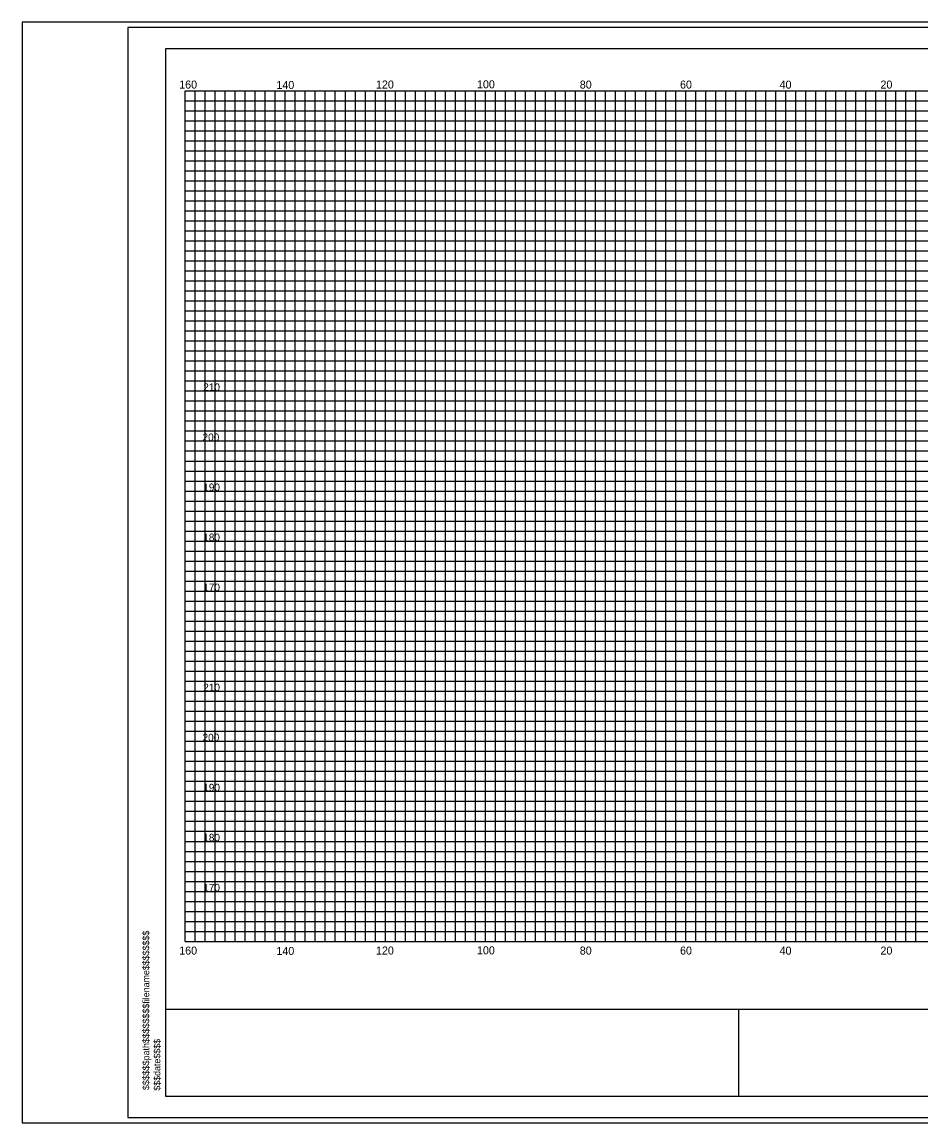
# Model space of a CAD drawing. Extents: x 967 to 1326, y 964 to 3144.
# Drawn here: x 967.4 to 1147, y 2083.7 to 2303.7 of the extents above; entities that cross this region are included whole.
import ezdxf

# ---------------------------------------------------------------- set-up
doc = ezdxf.new("R2010")
doc.units = 0
for name, color, linetype in [('Default', 7, 'Continuous'), ('RD_GPK_XS_Cell', 7, 'Continuous'), ('RD_XS_ExGround', 7, 'Continuous'), ('RD_XS_ExPaveRet', 7, 'Continuous'), ('RD_XS_Misc_Line', 7, 'Continuous'), ('RD_XS_TX_Elev_EX', 7, 'Continuous'), ('RD_XS_TX_Station', 7, 'Continuous')]:
    doc.layers.add(name, color=color, linetype=linetype)

msp = doc.modelspace()

# ---------------------------------------------------------------- linework, layer by layer
at = {"layer": 'RD_GPK_XS_Cell'}
for p, q in [((1000, 2290), (1320, 2290)), ((1000, 2120), (1000, 2290)), ((1010, 2120), (1010, 2290)), ((1020, 2120), (1020, 2290)), ((1030, 2120), (1030, 2290)), ((1040, 2120), (1040, 2290)), ((1050, 2120), (1050, 2290)), ((1060, 2120), (1060, 2290)), ((1070, 2120), (1070, 2290)), ((1080, 2120), (1080, 2290)), ((1090, 2120), (1090, 2290)), ((1100, 2120), (1100, 2290)), ((1110, 2120), (1110, 2290)), ((1120, 2120), (1120, 2290)), ((1130, 2120), (1130, 2290)), ((1140, 2120), (1140, 2290)), ((1000, 2280), (1320, 2280)), ((1000, 2270), (1320, 2270)), ((1000, 2260), (1320, 2260)), ((1000, 2250), (1320, 2250)), ((1000, 2240), (1320, 2240)), ((1000, 2230), (1320, 2230)), ((1000, 2220), (1320, 2220)), ((1000, 2210), (1320, 2210)), ((1000, 2200), (1320, 2200)), ((1000, 2190), (1320, 2190)), ((1000, 2180), (1320, 2180)), ((1000, 2170), (1320, 2170)), ((1000, 2160), (1320, 2160)), ((1000, 2150), (1320, 2150)), ((1000, 2140), (1320, 2140)), ((1000, 2130), (1320, 2130)), ((1000, 2120), (1320, 2120))]:
    msp.add_line(p, q, dxfattribs=at)
at = {"layer": 'RD_XS_ExGround'}
for p, q in [((1000, 2288), (1320, 2288)), ((1002, 2120), (1002, 2290)), ((1004, 2120), (1004, 2290)), ((1006, 2120), (1006, 2290)), ((1008, 2120), (1008, 2290)), ((1012, 2120), (1012, 2290)), ((1014, 2120), (1014, 2290)), ((1016, 2120), (1016, 2290)), ((1018, 2120), (1018, 2290)), ((1022, 2120), (1022, 2290)), ((1024, 2120), (1024, 2290)), ((1026, 2120), (1026, 2290)), ((1028, 2120), (1028, 2290)), ((1032, 2120), (1032, 2290)), ((1034, 2120), (1034, 2290)), ((1036, 2120), (1036, 2290)), ((1038, 2120), (1038, 2290)), ((1042, 2120), (1042, 2290)), ((1044, 2120), (1044, 2290)), ((1046, 2120), (1046, 2290)), ((1048, 2120), (1048, 2290)), ((1052, 2120), (1052, 2290)), ((1054, 2120), (1054, 2290)), ((1056, 2120), (1056, 2290)), ((1058, 2120), (1058, 2290)), ((1062, 2120), (1062, 2290)), ((1064, 2120), (1064, 2290)), ((1066, 2120), (1066, 2290)), ((1068, 2120), (1068, 2290)), ((1072, 2120), (1072, 2290)), ((1074, 2120), (1074, 2290)), ((1076, 2120), (1076, 2290)), ((1078, 2120), (1078, 2290)), ((1082, 2120), (1082, 2290)), ((1084, 2120), (1084, 2290)), ((1086, 2120), (1086, 2290)), ((1088, 2120), (1088, 2290)), ((1092, 2120), (1092, 2290)), ((1094, 2120), (1094, 2290)), ((1096, 2120), (1096, 2290)), ((1098, 2120), (1098, 2290)), ((1102, 2120), (1102, 2290)), ((1104, 2120), (1104, 2290)), ((1106, 2120), (1106, 2290)), ((1108, 2120), (1108, 2290)), ((1112, 2120), (1112, 2290)), ((1114, 2120), (1114, 2290)), ((1116, 2120), (1116, 2290)), ((1118, 2120), (1118, 2290)), ((1122, 2120), (1122, 2290)), ((1124, 2120), (1124, 2290)), ((1126, 2120), (1126, 2290)), ((1128, 2120), (1128, 2290)), ((1132, 2120), (1132, 2290)), ((1134, 2120), (1134, 2290)), ((1136, 2120), (1136, 2290)), ((1138, 2120), (1138, 2290)), ((1142, 2120), (1142, 2290)), ((1144, 2120), (1144, 2290)), ((1146, 2120), (1146, 2290)), ((1000, 2286), (1320, 2286)), ((1000, 2284), (1320, 2284)), ((1000, 2282), (1320, 2282)), ((1000, 2278), (1320, 2278)), ((1000, 2276), (1320, 2276)), ((1000, 2274), (1320, 2274)), ((1000, 2272), (1320, 2272)), ((1000, 2268), (1320, 2268)), ((1000, 2266), (1320, 2266)), ((1000, 2264), (1320, 2264)), ((1000, 2262), (1320, 2262)), ((1000, 2258), (1320, 2258)), ((1000, 2256), (1320, 2256)), ((1000, 2254), (1320, 2254)), ((1000, 2252), (1320, 2252)), ((1000, 2248), (1320, 2248)), ((1000, 2246), (1320, 2246)), ((1000, 2244), (1320, 2244)), ((1000, 2242), (1320, 2242)), ((1000, 2238), (1320, 2238)), ((1000, 2236), (1320, 2236)), ((1000, 2234), (1320, 2234)), ((1000, 2232), (1320, 2232)), ((1000, 2228), (1320, 2228)), ((1000, 2226), (1320, 2226)), ((1000, 2224), (1320, 2224)), ((1000, 2222), (1320, 2222)), ((1000, 2218), (1320, 2218)), ((1000, 2216), (1320, 2216)), ((1000, 2214), (1320, 2214)), ((1000, 2212), (1320, 2212)), ((1000, 2208), (1320, 2208)), ((1000, 2206), (1320, 2206)), ((1000, 2204), (1320, 2204)), ((1000, 2202), (1320, 2202)), ((1000, 2198), (1320, 2198)), ((1000, 2196), (1320, 2196)), ((1000, 2194), (1320, 2194)), ((1000, 2192), (1320, 2192)), ((1000, 2188), (1320, 2188)), ((1000, 2186), (1320, 2186)), ((1000, 2184), (1320, 2184)), ((1000, 2182), (1320, 2182)), ((1000, 2178), (1320, 2178)), ((1000, 2176), (1320, 2176)), ((1000, 2174), (1320, 2174)), ((1000, 2172), (1320, 2172)), ((1000, 2168), (1320, 2168)), ((1000, 2166), (1320, 2166)), ((1000, 2164), (1320, 2164)), ((1000, 2162), (1320, 2162)), ((1000, 2158), (1320, 2158)), ((1000, 2156), (1320, 2156)), ((1000, 2154), (1320, 2154)), ((1000, 2152), (1320, 2152)), ((1000, 2148), (1320, 2148)), ((1000, 2146), (1320, 2146)), ((1000, 2144), (1320, 2144)), ((1000, 2142), (1320, 2142)), ((1000, 2138), (1320, 2138)), ((1000, 2136), (1320, 2136)), ((1000, 2134), (1320, 2134)), ((1000, 2132), (1320, 2132)), ((1000, 2128), (1320, 2128)), ((1000, 2126), (1320, 2126)), ((1000, 2124), (1320, 2124)), ((1000, 2122), (1320, 2122))]:
    msp.add_line(p, q, dxfattribs=at)
at = {"layer": 'RD_XS_ExPaveRet'}
for points in [[(967.41, 2083.72), (1326.28, 2083.72), (1326.28, 2303.72), (967.41, 2303.72)], [(988.52, 2084.84), (1326.28, 2084.84), (1326.28, 2302.6), (988.52, 2302.6)]]:
    msp.add_lwpolyline(points, close=True, dxfattribs=at)
at = {"layer": 'RD_XS_TX_Elev_EX'}
for p, q in [((996.11, 2088.98), (996.11, 2298.46)), ((996.11, 2298.46), (1323.89, 2298.46)), ((996.11, 2106.49), (1323.89, 2106.49)), ((1110.59, 2088.98), (1110.59, 2106.56)), ((1323.89, 2088.98), (996.11, 2088.98))]:
    msp.add_line(p, q, dxfattribs=at)
at = {"layer": 'RD_XS_TX_Station'}
msp.add_lwpolyline([(967.41, 2083.72), (1326.28, 2083.72), (1326.28, 2303.72), (967.41, 2303.72)], close=True, dxfattribs=at)

# ---------------------------------------------------------------- texts
at = {"layer": 'Default'}
for s, p in [('210', (1003.61, 2230)), ('200', (1003.47, 2220)), ('190', (1003.61, 2210)), ('180', (1003.61, 2200)), ('170', (1003.61, 2190)), ('210', (1003.61, 2170)), ('200', (1003.47, 2160)), ('190', (1003.61, 2150)), ('180', (1003.61, 2140)), ('170', (1003.61, 2130))]:
    msp.add_text(s, height=1.5, dxfattribs=at).set_placement(p)
for s, p in [('$$$$$$path$$$$$$$$filename$$$$$$$$', (992.83, 2090.31)), ('$$$date$$$$', (995.04, 2090.17))]:
    msp.add_text(s, height=1.3258, rotation=90, dxfattribs=at).set_placement(p)
at = {"layer": 'RD_XS_Misc_Line'}
for s, p in [('160', (998.81, 2290.42)), ('140', (1018.23, 2290.34)), ('120', (1038.12, 2290.43)), ('100', (1058.3, 2290.47)), ('80', (1078.84, 2290.42)), ('60', (1098.86, 2290.42)), ('40', (1118.75, 2290.41)), ('20', (1138.91, 2290.42)), ('160', (998.81, 2117.37)), ('140', (1018.23, 2117.29)), ('120', (1038.12, 2117.38)), ('100', (1058.3, 2117.42)), ('80', (1078.84, 2117.37)), ('60', (1098.86, 2117.37)), ('40', (1118.75, 2117.36)), ('20', (1138.91, 2117.37))]:
    msp.add_text(s, height=1.6, dxfattribs=at).set_placement(p)

doc.saveas('drawing.dxf')
